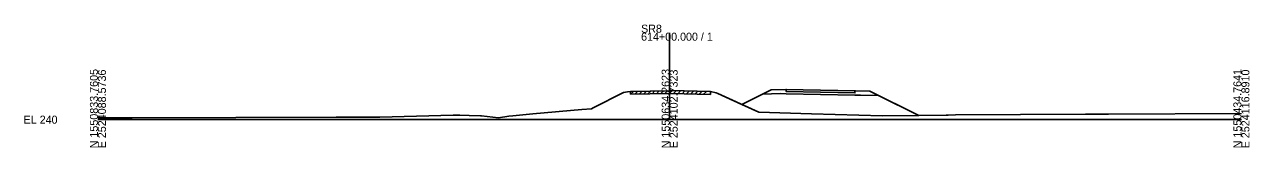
# Model space of a CAD drawing. Extents: x -26 to 2803, y -10 to 19537.
# Drawn here: x -25.7 to 402.8, y 18990.3 to 19033.2 of the extents above; entities that cross this region are included whole.
import ezdxf

# ---------------------------------------------------------------- set-up
doc = ezdxf.new("R2010")
doc.units = 0
for name, color, linetype in [('50', 7, 'Continuous'), ('XS_CELL', 7, 'Continuous'), ('XS_M_MULTI', 7, 'Continuous'), ('XS_M_SHAPES_EARTHWORK', 7, 'Continuous'), ('XS_P_FINISHED_GRADE', 7, 'Continuous'), ('XS_P_SUBGRADE_GRANULAR', 7, 'Continuous'), ('XS_P_SUBGRADE_PAVEMENT', 7, 'Continuous'), ('XS_X_GROUND', 7, 'Continuous')]:
    doc.layers.add(name, color=color, linetype=linetype)

msp = doc.modelspace()

# ---------------------------------------------------------------- linework, layer by layer
at = {"layer": '50'}
for p, q in [((186.35, 19008.85), (187.37, 19009.87)), ((186.35, 19008.85), (186.35, 19009.85)), ((187.85, 19008.88), (188.87, 19009.9)), ((189.35, 19008.91), (190.37, 19009.93)), ((190.85, 19008.94), (191.87, 19009.96)), ((192.35, 19008.96), (193.37, 19009.98)), ((193.85, 19008.99), (194.87, 19010.01)), ((195.35, 19009.02), (196.37, 19010.04)), ((196.85, 19009.05), (197.87, 19010.07)), ((198.35, 19009.08), (199.37, 19010.1)), ((199.85, 19009.1), (200.85, 19010.11)), ((201.35, 19009.1), (202.33, 19010.08)), ((202.85, 19009.06), (203.83, 19010.04)), ((204.35, 19009.03), (205.33, 19010.01)), ((205.85, 19009), (206.83, 19009.98)), ((207.35, 19008.97), (208.33, 19009.95)), ((208.85, 19008.94), (209.83, 19009.92)), ((210.35, 19008.91), (211.33, 19009.89)), ((211.85, 19008.87), (212.83, 19009.85)), ((214.29, 19009.82), (214.29, 19008.82)), ((186.35, 19008.85), (200, 19009.11)), ((200, 19009.11), (200.46, 19009.12)), ((200.46, 19009.12), (214.29, 19008.82))]:
    msp.add_line(p, q, dxfattribs=at)
at = {"layer": 'XS_CELL'}
for p, q in [((200, 19000), (200, 19030.35)), ((0, 19000), (200, 19000)), ((200, 19000), (400, 19000))]:
    msp.add_line(p, q, dxfattribs=at)
at = {"layer": 'XS_M_MULTI'}
for p, q in [((225.25, 19005.31), (235.53, 19010.37)), ((235.53, 19010.37), (240.61, 19010.57)), ((240.61, 19010.57), (252.8, 19010.33)), ((252.8, 19010.33), (264.98, 19010.09)), ((264.98, 19010.09), (270.06, 19009.89)), ((270.06, 19009.89), (287.15, 19001.48))]:
    msp.add_line(p, q, dxfattribs=at)
for points in [[(0, 19000.61), (11.66, 19000.64), (11.97, 19000.64), (48.22, 19000.7), (83.31, 19000.83), (83.63, 19000.83), (96.59, 19000.88), (98.63, 19000.89), (124.26, 19001.52), (126.55, 19001.57), (129.82, 19001.47), (133.77, 19001.34), (134.2, 19001.33), (140.14, 19000.64), (143.79, 19001.17), (145.08, 19001.36), (152.09, 19001.98), (169.22, 19003.5), (172.71, 19003.81), (173.25, 19004.09), (183.88, 19009.5), (185.2, 19009.69), (186.35, 19009.85), (200, 19010.11), (200.46, 19010.12), (214.29, 19009.82), (216.27, 19009.38), (216.89, 19009.1), (225.25, 19005.31)], [(287.15, 19001.48), (296.72, 19001.61), (297.41, 19001.62), (299.99, 19001.72), (345.47, 19001.87), (346.17, 19001.88), (347.8, 19001.89), (348.21, 19001.89), (348.87, 19001.89), (350.14, 19001.9), (353.55, 19001.92), (400, 19002.17)]]:
    msp.add_lwpolyline(points, dxfattribs=at)
at = {"layer": 'XS_M_SHAPES_EARTHWORK'}
for points in [[(270.06, 19009.89), (273.04, 19008.43), (266.8, 19008.55), (264.8, 19008.59), (252.8, 19008.83), (240.8, 19009.07), (238.8, 19009.11), (232.46, 19008.86), (235.53, 19010.37), (240.61, 19010.57), (240.8, 19010.57), (240.8, 19009.82), (252.8, 19009.58), (264.8, 19009.34), (264.8, 19010.1), (264.98, 19010.09)], [(240.8, 19010.57), (252.8, 19010.33), (264.8, 19010.1), (264.8, 19009.34), (252.8, 19009.58), (240.8, 19009.82)], [(240.8, 19009.07), (252.8, 19008.83), (264.8, 19008.59), (266.8, 19008.55), (273.04, 19008.43), (287.15, 19001.48), (286.59, 19001.47), (274.45, 19001.31), (249.61, 19002.05), (231.24, 19002.6), (225.25, 19005.31), (232.46, 19008.86), (238.8, 19009.11)]]:
    msp.add_lwpolyline(points, close=True, dxfattribs=at)
at = {"layer": 'XS_P_FINISHED_GRADE'}
for p, q in [((235.53, 19010.37), (225.25, 19005.31)), ((240.61, 19010.57), (235.53, 19010.37)), ((240.61, 19010.57), (252.8, 19010.33)), ((252.8, 19010.33), (264.98, 19010.09)), ((264.98, 19010.09), (270.06, 19009.89)), ((270.06, 19009.89), (287.15, 19001.48))]:
    msp.add_line(p, q, dxfattribs=at)
at = {"layer": 'XS_P_SUBGRADE_GRANULAR'}
for p, q in [((238.8, 19009.11), (232.46, 19008.86)), ((240.8, 19009.07), (238.8, 19009.11)), ((240.8, 19009.07), (252.8, 19008.83)), ((252.8, 19008.83), (264.8, 19008.59)), ((264.8, 19008.59), (266.8, 19008.55)), ((266.8, 19008.55), (273.04, 19008.43))]:
    msp.add_line(p, q, dxfattribs=at)
at = {"layer": 'XS_P_SUBGRADE_PAVEMENT'}
for p, q in [((240.8, 19009.82), (240.8, 19010.57)), ((240.8, 19009.82), (252.8, 19009.58)), ((264.8, 19009.34), (264.8, 19010.1)), ((252.8, 19009.58), (264.8, 19009.34))]:
    msp.add_line(p, q, dxfattribs=at)
at = {"layer": 'XS_X_GROUND'}
msp.add_lwpolyline([(0, 19000.61), (11.66, 19000.64), (11.97, 19000.64), (48.22, 19000.7), (83.31, 19000.83), (83.63, 19000.83), (96.59, 19000.88), (98.63, 19000.89), (124.26, 19001.52), (126.55, 19001.57), (129.82, 19001.47), (133.77, 19001.34), (134.2, 19001.33), (140.14, 19000.64), (143.79, 19001.17), (145.08, 19001.36), (152.09, 19001.98), (169.22, 19003.5), (172.71, 19003.81), (173.25, 19004.09), (183.88, 19009.5), (185.2, 19009.69), (186.35, 19009.85), (200, 19010.11), (200.46, 19010.12), (214.29, 19009.82), (216.27, 19009.38), (216.89, 19009.1), (231.24, 19002.6), (249.61, 19002.05), (274.45, 19001.31), (286.59, 19001.47), (296.72, 19001.61), (297.41, 19001.62), (299.99, 19001.72), (345.47, 19001.87), (346.17, 19001.88), (347.8, 19001.89), (348.21, 19001.89), (348.87, 19001.89), (350.14, 19001.9), (353.55, 19001.92), (400, 19002.17)], dxfattribs=at)

# ---------------------------------------------------------------- texts
at = {"layer": 'XS_CELL'}
for s, p in [('SR8', (190, 19030.35)), ('614+00.000 / 1', (190, 19027.55)), ('EL 240', (-26, 18998.6))]:
    msp.add_text(s, height=2.8, dxfattribs=at).set_placement(p)
for s, p in [('N 1550833.7605', (0, 18990)), ('E 2524088.5736', (2.8, 18990)), ('N 1550634.2623', (200, 18990)), ('E 2524102.7323', (202.8, 18990)), ('N 1550434.7641', (400, 18990)), ('E 2524116.8910', (402.8, 18990))]:
    msp.add_text(s, height=2.8, rotation=90, dxfattribs=at).set_placement(p)

doc.saveas('drawing.dxf')
